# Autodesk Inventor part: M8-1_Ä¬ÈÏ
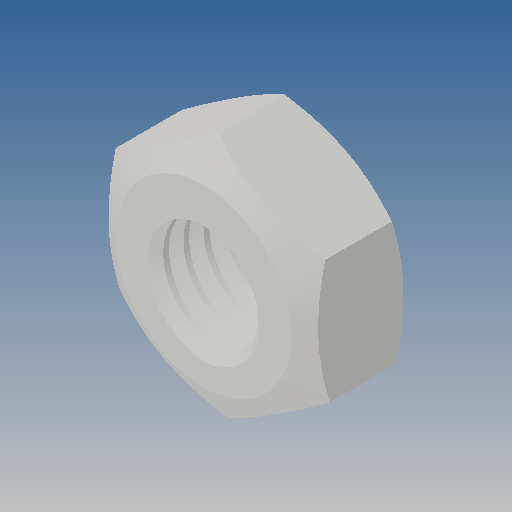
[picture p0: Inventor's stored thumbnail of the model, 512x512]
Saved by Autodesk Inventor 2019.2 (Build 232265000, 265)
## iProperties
Created: 2010-06
Part Number: M8-1_Ä¬ÈÏ
Material: Ogólny
Document SubType Name: Modeling
Designer: CADENGINEERING4
Density: 1 g/cm^3
Appearance: Domyślna
Author: CADENGINEERING4
Revision Number: ÈÎºÎ
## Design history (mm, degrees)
feature "NONE"
node "Bryła1"
